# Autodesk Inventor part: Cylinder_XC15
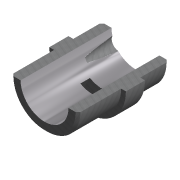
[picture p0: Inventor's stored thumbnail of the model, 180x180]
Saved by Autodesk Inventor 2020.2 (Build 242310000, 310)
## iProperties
Created: 2000-05
Part Number: Cylinder_XC15
Document SubType Name: Modeling
Designer: F.Stasiak
Stock Number: Cylinder_XC15
Density: 2.7 g/cm^3
Material: Aluminium 6061
Appearance: Aluminium (obrabiane)
Mass: 2050.73 g
Surface Area: 948.052 cm^2
Volume: 759.531 cm^3
Catalog Web Link: www.expertbooks.pl
Manager: www.cadconsulting.pl
Company: Fabian Stasiak CAD Consulting
Control State: 0
Master: False
Checked Out: False
Shininess: 0.0
Density: 0.0
Volumn: 0.0
Area: 0.0
PropertySet Name: Model Information
Author: F.Stasiak
Subject: Zbiór ćwiczeń. Autodesk Inventor 2020. Kurs Professional
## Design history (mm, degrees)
node "Base1"
feature "Podział1"
node "Bryła1"
node "Korpusy bryłowe"
node "Korpusy powierzchniowe"
